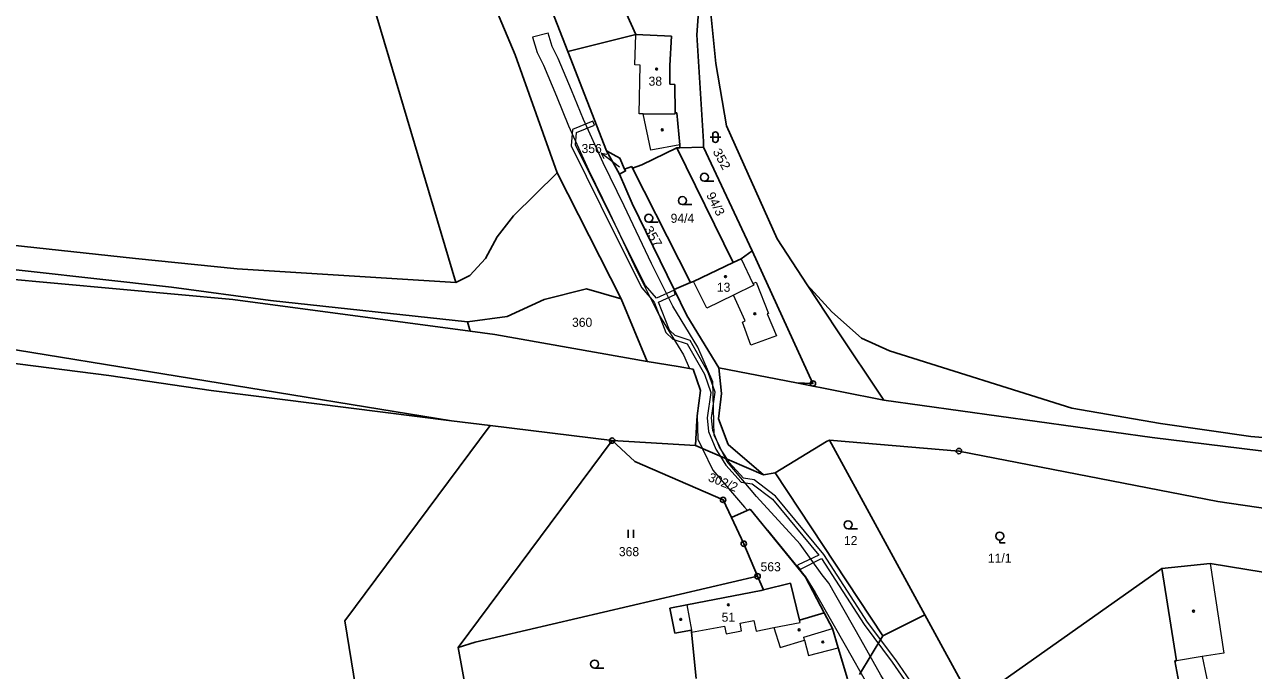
# Model space of a CAD drawing. Extents: x -769392 to -767038, y -1018329 to -1015269.
# Drawn here: x -768677.7 to -768447.4, y -1016206.6 to -1016085.5 of the extents above; entities that cross this region are included whole.
import ezdxf
from ezdxf.enums import TextEntityAlignment as Align

# ---------------------------------------------------------------- set-up
doc = ezdxf.new("R2010")
doc.units = 0
doc.header["$LTSCALE"] = 0.68
for name, color, linetype, lineweight in [('1', 7, 'Continuous', 25), ('13', 7, 'Continuous', 13), ('3', 7, 'Continuous', 25), ('4', 7, 'Continuous', 13), ('5', 7, 'Continuous', 25), ('7', 7, 'Continuous', 13), ('8', 7, 'Continuous', 25)]:
    doc.layers.add(name, color=color, linetype=linetype, lineweight=lineweight)
doc.layers.add('2', color=7, linetype='Continuous')

msp = doc.modelspace()

# ---------------------------------------------------------------- linework, layer by layer
at = {"layer": '1'}
for p, q in [((-768563.14, -1016087.38), (-768577.15, -1016056.29)), ((-768575.9, -1016090.56), (-768563.14, -1016087.38)), ((-768563.14, -1016087.38), (-768556.45, -1016087.71)), ((-768556.45, -1016087.71), (-768556.82, -1016093.19)), ((-768568.66, -1016109.18), (-768575.9, -1016090.56)), ((-768556.82, -1016093.19), (-768556.8, -1016096.71)), ((-768556.8, -1016096.71), (-768555.84, -1016096.72)), ((-768555.84, -1016096.72), (-768555.81, -1016102.03)), ((-768555.81, -1016102.03), (-768555.48, -1016102.05)), ((-768555.48, -1016102.05), (-768554.94, -1016108.07)), ((-768566.24, -1016113.52), (-768568.66, -1016109.18)), ((-768555.48, -1016108.62), (-768562.02, -1016111.78)), ((-768554.89, -1016108.61), (-768555.48, -1016108.62)), ((-768555.48, -1016108.62), (-768544.94, -1016130.13)), ((-768554.94, -1016108.07), (-768554.89, -1016108.61)), ((-768554.89, -1016108.61), (-768550.51, -1016108.5)), ((-768541.33, -1016127.95), (-768550.51, -1016108.5)), ((-768562.02, -1016111.78), (-768563.76, -1016112.43)), ((-768565.92, -1016136.91), (-768577.92, -1016113.27)), ((-768565.29, -1016112.62), (-768563.93, -1016112.09)), ((-768563.93, -1016112.09), (-768563.76, -1016112.43)), ((-768563.76, -1016112.43), (-768552.9, -1016133.88)), ((-768543.43, -1016129.41), (-768541.33, -1016127.95)), ((-768544.94, -1016130.13), (-768552.33, -1016133.67)), ((-768544.94, -1016130.13), (-768543.43, -1016129.41)), ((-768552.9, -1016133.88), (-768555.98, -1016135.17)), ((-768552.33, -1016133.67), (-768552.9, -1016133.88)), ((-768561.03, -1016148.63), (-768565.92, -1016136.91)), ((-768594.7, -1016141.25), (-768594.18, -1016142.99)), ((-768533.04, -1016152.63), (-768547.6, -1016149.84)), ((-768516.66, -1016155.93), (-768533.04, -1016152.63)), ((-768590.44, -1016160.65), (-768597.68, -1016159.76)), ((-768567.62, -1016163.49), (-768590.44, -1016160.65)), ((-768596.46, -1016202.24), (-768567.62, -1016163.49)), ((-768552.01, -1016164.43), (-768567.62, -1016163.49)), ((-768539.24, -1016169.93), (-768552.01, -1016164.43)), ((-768537.07, -1016169.5), (-768527.44, -1016163.64)), ((-768527.44, -1016163.64), (-768526.84, -1016163.38)), ((-768508.98, -1016196.12), (-768526.84, -1016163.38)), ((-768539.24, -1016169.93), (-768537.07, -1016169.5)), ((-768516.86, -1016200.1), (-768537.07, -1016169.5)), ((-768541.75, -1016176.36), (-768545.25, -1016177.91)), ((-768531.35, -1016189.1), (-768541.75, -1016176.36)), ((-768542.93, -1016182.82), (-768545.25, -1016177.91)), ((-768540.35, -1016188.9), (-768542.93, -1016182.82)), ((-768464.56, -1016187.45), (-768500.05, -1016212.5)), ((-768455.51, -1016186.52), (-768464.56, -1016187.45)), ((-768461.82, -1016204.77), (-768464.56, -1016187.45)), ((-768434.6, -1016189.95), (-768455.51, -1016186.52)), ((-768593.29, -1016201.29), (-768540.35, -1016188.9)), ((-768540.35, -1016188.9), (-768539.25, -1016191.48)), ((-768539.25, -1016191.48), (-768534.19, -1016190.2)), ((-768534.19, -1016190.2), (-768532.47, -1016197.12)), ((-768527.87, -1016195.76), (-768531.35, -1016189.1)), ((-768553.61, -1016194.29), (-768539.68, -1016191.59)), ((-768539.68, -1016191.59), (-768539.25, -1016191.48)), ((-768556.8, -1016194.87), (-768553.61, -1016194.29)), ((-768555.83, -1016199.56), (-768556.8, -1016194.87)), ((-768532.47, -1016197.12), (-768527.87, -1016195.76)), ((-768527.87, -1016195.76), (-768526.3, -1016198.72)), ((-768508.98, -1016196.12), (-768516.86, -1016200.1)), ((-768500.05, -1016212.5), (-768508.98, -1016196.12)), ((-768552.73, -1016199.03), (-768555.83, -1016199.56)), ((-768552.72, -1016199.41), (-768552.73, -1016199.03)), ((-768551.88, -1016208.04), (-768552.72, -1016199.41)), ((-768526.3, -1016198.72), (-768525.24, -1016202.34)), ((-768596.46, -1016202.24), (-768593.29, -1016201.29)), ((-768521.22, -1016207.35), (-768516.86, -1016200.1)), ((-768592.42, -1016224.53), (-768596.46, -1016202.24)), ((-768525.24, -1016202.34), (-768523.51, -1016208.11)), ((-768462.15, -1016204.79), (-768461.82, -1016204.77)), ((-768461.37, -1016208.75), (-768462.15, -1016204.79))]:
    msp.add_line(p, q, dxfattribs=at)
for points in [[(-768577.92, -1016113.27), (-768585.77, -1016091.21), (-768590.28, -1016080.47), (-768600.78, -1016062.99), (-768610.85, -1016040.44), (-768623.52, -1016016.53), (-768630.25, -1016001.25), (-768662.38, -1015939.85), (-768680.7, -1015896.15), (-768688.37, -1015880.1), (-768704.55, -1015891.41)], [(-768647.11, -1015990.45), (-768631.35, -1016018.03), (-768596.9, -1016133.83)], [(-768531.03, -1016134.27), (-768536.67, -1016125.7), (-768546.18, -1016104.49), (-768548.19, -1016092.82), (-768549.32, -1016081.54), (-768548.21, -1016066.2), (-768550.18, -1016059.91), (-768553.38, -1016055.35), (-768557.44, -1016050.38), (-768570.36, -1016038.63), (-768574.11, -1016035.31), (-768603.29, -1016008.55), (-768604.7, -1016006.61), (-768608.35, -1016002)], [(-768575.9, -1016090.56), (-768582.47, -1016073.67), (-768591.21, -1016051.31)], [(-768559.94, -1016051.82), (-768553.83, -1016058.45), (-768551.98, -1016060.85), (-768550.95, -1016063.59), (-768550.23, -1016066.43), (-768551.76, -1016087.46), (-768550.46, -1016107.42), (-768550.51, -1016108.5)], [(-768568.66, -1016109.18), (-768566.15, -1016110.55), (-768565.29, -1016112.62)], [(-768596.9, -1016133.83), (-768594.27, -1016132.53), (-768591.35, -1016129.34), (-768589.18, -1016125.28), (-768586.1, -1016121.35), (-768577.92, -1016113.27)], [(-768566.24, -1016113.52), (-768565.08, -1016112.93), (-768565.29, -1016112.62)], [(-768555.98, -1016135.17), (-768563.88, -1016119.04), (-768566.24, -1016113.52)], [(-769077.57, -1016120.97), (-769051.96, -1016123.35), (-768998.31, -1016124.28), (-768965.15, -1016122.6), (-768902.06, -1016120.44), (-768865.37, -1016119.73), (-768805.12, -1016118.98), (-768769.94, -1016115), (-768749.97, -1016114.84), (-768736.74, -1016116.15), (-768689.9, -1016125.81), (-768656.93, -1016129.38), (-768637.88, -1016131.28), (-768596.9, -1016133.83)], [(-768594.7, -1016141.25), (-768631.63, -1016137.21), (-768650.19, -1016134.74), (-768717.39, -1016127.21), (-768738.73, -1016121.28), (-768749.98, -1016120.03), (-768769.94, -1016120.01), (-768778.71, -1016121.23), (-768783.28, -1016122.74), (-768840.7, -1016124.64), (-768865.08, -1016124.72), (-768902.28, -1016125.77), (-768936.05, -1016127.23), (-768965.85, -1016127.81), (-768998.75, -1016129.36), (-769048.63, -1016129.62)], [(-769048.63, -1016129.62), (-769041.93, -1016130.68), (-768986.37, -1016130.93), (-768927.89, -1016128.95), (-768776.02, -1016126.01), (-768730.41, -1016128.41), (-768682.51, -1016133.05), (-768638.7, -1016137.06), (-768594.18, -1016142.99)], [(-768533.04, -1016152.63), (-768529.97, -1016152.78), (-768541.33, -1016127.95)], [(-768565.92, -1016136.91), (-768572.39, -1016135.03), (-768580.34, -1016137.07), (-768587.25, -1016140.25), (-768594.7, -1016141.25)], [(-768516.66, -1016155.93), (-768525.6, -1016142.53), (-768531.03, -1016134.27)], [(-768308.65, -1016180.07), (-768333.05, -1016176.93), (-768332.77, -1016170.45), (-768346.58, -1016171.01), (-768374.45, -1016169.36), (-768404.04, -1016166.38), (-768447.93, -1016162.69), (-768464.85, -1016160.27), (-768481.43, -1016157.38), (-768515.64, -1016146.68), (-768520.87, -1016144.31), (-768526.44, -1016139.35), (-768531.03, -1016134.27)], [(-768597.68, -1016159.76), (-768689.84, -1016144.77), (-768728.2, -1016140.14), (-768798.42, -1016136.61), (-768801.46, -1016136.73)], [(-768547.6, -1016149.84), (-768553.63, -1016140.05), (-768555.98, -1016135.17)], [(-768800.7, -1016141.18), (-768780.54, -1016141.96), (-768763.47, -1016143.95), (-768743.59, -1016145.04), (-768717.78, -1016145.65), (-768694.95, -1016147.16), (-768681.5, -1016148.79), (-768661.91, -1016151.26), (-768642.73, -1016154.07), (-768597.68, -1016159.76)], [(-768594.18, -1016142.99), (-768589.61, -1016143.6), (-768561.03, -1016148.63)], [(-768561.03, -1016148.63), (-768555.23, -1016149.61), (-768552.44, -1016150.1), (-768551.03, -1016154.09), (-768551.65, -1016158.86), (-768551.7, -1016159.73), (-768552.01, -1016164.43)], [(-768539.24, -1016169.93), (-768545.85, -1016164.19), (-768547.66, -1016159.38), (-768547.1, -1016154.63), (-768547.6, -1016149.84)], [(-768265.65, -1016186.8), (-768267.45, -1016188.93), (-768339.18, -1016177.1), (-768385.9, -1016172.79), (-768466.41, -1016162.88), (-768516.66, -1016155.93)], [(-768621.96, -1016276.21), (-768609.16, -1016249.91), (-768617.69, -1016197.27), (-768590.44, -1016160.65)], [(-768545.25, -1016177.91), (-768546.81, -1016174.59), (-768563.33, -1016167.39), (-768567.62, -1016163.49)], [(-768526.84, -1016163.38), (-768502.6, -1016165.44), (-768454.1, -1016174.88), (-768401.6, -1016182.57)]]:
    msp.add_lwpolyline(points, dxfattribs=at)
at = {"layer": '13'}
for points in [[(-768506.93, -1016223.11), (-768512.05, -1016215.74), (-768517.25, -1016207.46), (-768520.98, -1016200.75), (-768527.01, -1016190.22), (-768528.22, -1016188.66), (-768532.37, -1016182.87), (-768540.52, -1016173.96), (-768546.13, -1016167.31), (-768546.34, -1016166.87), (-768548.49, -1016162.47), (-768548.7, -1016152.45), (-768551.52, -1016145.96), (-768556.22, -1016138.29), (-768560.24, -1016130.3), (-768565.36, -1016119.48), (-768569.27, -1016111.41), (-768572.99, -1016103.31), (-768575.19, -1016097.78), (-768577.71, -1016091.86), (-768578.82, -1016089.6), (-768579.58, -1016087.11), (-768582.55, -1016087.86)], [(-768582.55, -1016087.86), (-768581.68, -1016090.73), (-768580.49, -1016093.14), (-768578.03, -1016098.94), (-768575.81, -1016104.52), (-768572.04, -1016112.71), (-768568.12, -1016120.8), (-768563, -1016131.64), (-768558.9, -1016139.78), (-768554.24, -1016147.38), (-768553.1, -1016149.98), (-768552.44, -1016150.1), (-768551.03, -1016154.09), (-768551.65, -1016158.86), (-768551.53, -1016163.22), (-768550.65, -1016165.01), (-768548.71, -1016169), (-768542.82, -1016175.98), (-768542.23, -1016176.57), (-768541.75, -1016176.36), (-768538.68, -1016180.12), (-768538.51, -1016180.29), (-768531.38, -1016188.99), (-768529.56, -1016191.93), (-768523.65, -1016202.25), (-768519.89, -1016209.02)], [(-768571.21, -1016103.61), (-768575.02, -1016105.16), (-768575.26, -1016108.23), (-768566.88, -1016125.16), (-768562.04, -1016134.86), (-768559.75, -1016137.51), (-768557.55, -1016143.24), (-768556.23, -1016144.47), (-768553.54, -1016145.37), (-768550.31, -1016151.03), (-768549.13, -1016154.45), (-768549.8, -1016159.19), (-768549.55, -1016161.79), (-768548.18, -1016165.09), (-768547.31, -1016166.45), (-768546.29, -1016168.06), (-768543.4, -1016171.27), (-768541.33, -1016171.6), (-768537.52, -1016174.45), (-768528.85, -1016184.94), (-768532.74, -1016186.78), (-768532.93, -1016186.93), (-768532.36, -1016187.64), (-768532.16, -1016187.49), (-768528.37, -1016185.59), (-768520.38, -1016197.95), (-768515.11, -1016205.02), (-768509.94, -1016212.51)], [(-768546, -1016167.02), (-768547.47, -1016164.72), (-768548.76, -1016161.59), (-768548.99, -1016159.21), (-768548.31, -1016154.38), (-768549.58, -1016150.7), (-768553, -1016144.71), (-768555.81, -1016143.77), (-768556.87, -1016142.78), (-768558.89, -1016137.51), (-768555.79, -1016136.1), (-768556, -1016135.31), (-768559.3, -1016136.81), (-768561.37, -1016134.42), (-768566.17, -1016124.81), (-768574.44, -1016108.07), (-768574.26, -1016105.72), (-768570.91, -1016104.36), (-768571.21, -1016103.61)], [(-768510.29, -1016210.6), (-768514.46, -1016204.55), (-768519.72, -1016197.5), (-768527.9, -1016184.83), (-768536.97, -1016173.87), (-768541.01, -1016170.84), (-768542.99, -1016170.53), (-768545.65, -1016167.57), (-768546, -1016167.02)]]:
    msp.add_lwpolyline(points, dxfattribs=at)
at = {"layer": '3'}
for p, q in [((-768549.251, -1016106.611), (-768547.249, -1016106.611)), ((-768548.751, -1016106.111), (-768548.751, -1016107.112)), ((-768547.749, -1016107.112), (-768547.749, -1016106.111)), ((-768550.313, -1016114.88), (-768548.563, -1016114.88)), ((-768554.423, -1016119.25), (-768552.673, -1016119.25)), ((-768560.753, -1016122.55), (-768559.003, -1016122.55)), ((-768564.601, -1016181.71), (-768564.601, -1016180.21)), ((-768563.6, -1016181.71), (-768563.6, -1016180.21)), ((-768523.373, -1016180), (-768521.623, -1016180)), ((-768570.883, -1016206.12), (-768569.133, -1016206.12))]:
    msp.add_line(p, q, dxfattribs=at)
msp.add_lwpolyline([(-768494.97, -1016182.142), (-768494.97, -1016182.64), (-768493.969, -1016182.64)], dxfattribs=at)
for centre in [(-768550.3129, -1016114.1298), (-768554.4229, -1016118.4998), (-768560.7529, -1016121.7998), (-768523.3729, -1016179.2498), (-768494.9693, -1016181.3909), (-768570.8829, -1016205.3698)]:
    msp.add_circle(centre, 0.75, dxfattribs=at)
for centre, start, end in [((-768548.25, -1016106.1109), 0, 180), ((-768548.25, -1016107.1109), 180, 359.98789)]:
    msp.add_arc(centre, 0.5, start, end, dxfattribs=at)
at = {"layer": '4'}
for p, q in [((-768563.38, -1016093.07), (-768563.14, -1016087.38)), ((-768562.33, -1016093.11), (-768563.38, -1016093.07)), ((-768562.52, -1016102.23), (-768562.33, -1016093.11)), ((-768561.76, -1016102.26), (-768562.52, -1016102.23)), ((-768561.76, -1016102.26), (-768555.79, -1016102.24)), ((-768560.34, -1016109.06), (-768561.76, -1016102.26)), ((-768555.79, -1016102.24), (-768555.81, -1016102.03)), ((-768554.94, -1016108.07), (-768560.34, -1016109.06)), ((-768543.43, -1016129.41), (-768541.23, -1016134.03)), ((-768549.88, -1016138.68), (-768552.33, -1016133.67)), ((-768541.06, -1016134.38), (-768544.87, -1016136.24)), ((-768541.23, -1016134.03), (-768540.61, -1016133.81)), ((-768541.23, -1016134.03), (-768541.06, -1016134.38)), ((-768540.61, -1016133.81), (-768538.29, -1016139.64)), ((-768544.87, -1016136.24), (-768549.88, -1016138.68)), ((-768542.67, -1016141.06), (-768544.87, -1016136.24)), ((-768538.29, -1016139.64), (-768538.55, -1016139.75)), ((-768543.19, -1016141.28), (-768542.67, -1016141.06)), ((-768541.6, -1016145.59), (-768543.19, -1016141.28)), ((-768538.55, -1016139.75), (-768536.77, -1016143.85)), ((-768536.77, -1016143.85), (-768541.6, -1016145.59)), ((-768455.51, -1016186.52), (-768452.94, -1016203.34)), ((-768553.61, -1016194.29), (-768552.73, -1016199.03)), ((-768543.59, -1016197.7), (-768541.03, -1016197.22)), ((-768541.03, -1016197.22), (-768540.63, -1016199.18)), ((-768532.35, -1016197.57), (-768532.47, -1016197.12)), ((-768552.72, -1016199.41), (-768546.55, -1016198.24)), ((-768546.55, -1016198.24), (-768546.25, -1016199.7)), ((-768546.25, -1016199.7), (-768543.34, -1016199.12)), ((-768543.34, -1016199.12), (-768543.59, -1016197.7)), ((-768540.63, -1016199.18), (-768537.28, -1016198.54)), ((-768537.28, -1016198.54), (-768532.35, -1016197.57)), ((-768537.28, -1016198.54), (-768536.09, -1016202.28)), ((-768531.67, -1016200.35), (-768526.3, -1016198.72)), ((-768536.09, -1016202.28), (-768531.55, -1016200.87)), ((-768531.55, -1016200.87), (-768531.67, -1016200.35)), ((-768531.55, -1016200.87), (-768530.82, -1016203.74)), ((-768530.82, -1016203.74), (-768525.24, -1016202.34)), ((-768457.02, -1016203.95), (-768461.82, -1016204.77)), ((-768452.94, -1016203.34), (-768457.02, -1016203.95)), ((-768457.02, -1016203.95), (-768450.36, -1016235.36))]:
    msp.add_line(p, q, dxfattribs=at)
at = {"layer": '5'}
for centre in [(-768559.2668, -1016093.8492), (-768558.1968, -1016105.2392), (-768546.3568, -1016132.7492), (-768540.8768, -1016139.6992), (-768545.8268, -1016194.2592), (-768554.7568, -1016196.9892), (-768458.6368, -1016195.4492), (-768532.5668, -1016198.9492), (-768528.1268, -1016201.2292)]:
    msp.add_circle(centre, 0.175, dxfattribs=at)
at = {"layer": '7'}
msp.add_line((-768569.687, -1016109.594), (-768569.188, -1016110.597), dxfattribs=at)
msp.add_lwpolyline([(-768566.21, -1016112.21), (-768567.29, -1016111.4), (-768569.687, -1016109.594), (-768568.586, -1016109.797)], dxfattribs=at)
at = {"layer": '8'}
for centre, radius in [((-768529.97, -1016152.7799), 0.5), ((-768529.97, -1016152.7799), 0.0303), ((-768567.62, -1016163.4899), 0.5), ((-768567.62, -1016163.4899), 0.0303), ((-768502.6, -1016165.4399), 0.5), ((-768502.6, -1016165.4399), 0.0303), ((-768546.81, -1016174.5899), 0.5), ((-768546.81, -1016174.5899), 0.0303), ((-768542.93, -1016182.8199), 0.5), ((-768542.93, -1016182.8199), 0.0303), ((-768540.35, -1016188.8999), 0.5), ((-768540.35, -1016188.8999), 0.0303)]:
    msp.add_circle(centre, radius, dxfattribs=at)

# ---------------------------------------------------------------- texts
at = {"layer": '2'}
for s, p in [('38', (-768559.509, -1016096.975)), ('356', (-768571.439, -1016109.595)), ('94/4', (-768554.429, -1016122.665)), ('13', (-768546.709, -1016135.595)), ('12', (-768522.899, -1016183.065)), ('11/1', (-768494.969, -1016186.365)), ('563', (-768537.889, -1016187.975)), ('51', (-768545.819, -1016197.425))]:
    msp.add_text(s, height=1.7, dxfattribs=at).set_placement(p, align=Align.CENTER)
at = {"layer": '2', "width": 1.1}
for s, rotation, p in [('352', 299, (-768548.821, -1016109.296)), ('357', 300, (-768561.678, -1016123.852))]:
    msp.add_text(s, height=1.7, rotation=rotation, dxfattribs=at).set_placement(p)
at = {"layer": '2', "width": 1.05}
msp.add_text('94/3', height=1.7, rotation=297, dxfattribs=at).set_placement((-768548.9586, -1016119.5086), align=Align.CENTER)
at = {"layer": '2'}
for s, p in [('360', (-768575.12, -1016142.165)), ('368', (-768566.34, -1016185.145))]:
    msp.add_text(s, height=1.7, dxfattribs=at).set_placement(p)
msp.add_text('302/2', height=1.7, rotation=338, dxfattribs=at).set_placement((-768547.1064, -1016172.0689), align=Align.CENTER)

doc.saveas('drawing.dxf')
